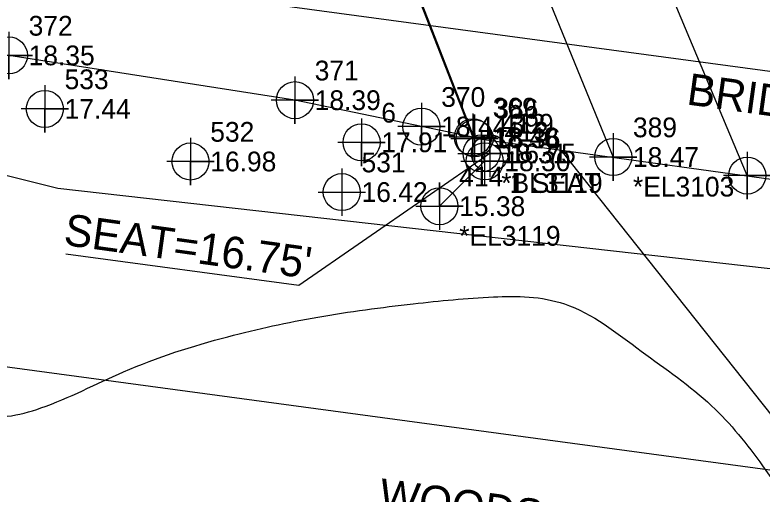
# Model space of a CAD drawing. Extents: x 2627243 to 2636458, y 566398 to 571062.
# Drawn here: x 2634518 to 2634612.5, y 569047.1 to 569107.7 of the extents above; entities that cross this region are included whole.
import ezdxf

# ---------------------------------------------------------------- set-up
doc = ezdxf.new("R2010")
doc.units = 0
for name, color, linetype in [('COGO Default Chain', 7, 'Continuous'), ('Cogo Default Point CELL', 7, 'Continuous'), ('COGO Default Point Elevation', 7, 'Continuous'), ('COGO Default Point Number', 7, 'Continuous'), ('Exist Horizontal Alignment', 7, 'Continuous'), ('Exist Horizontal T-Line Point CELL', 7, 'Continuous'), ('Exist Horizontal T-Line Point Cogo Elevation', 7, 'Continuous'), ('Exist Horizontal T-Line Point Cogo Number', 7, 'Continuous'), ('Exist Hydro Jurisdictional Stream or Body of Water', 7, 'Continuous'), ('Exist Right of Way Line', 7, 'Continuous'), ('Exist Roads EOP', 7, 'Continuous'), ('Exist Roads EOP Cogo Elevation', 7, 'Continuous'), ('Exist Roads EOP Cogo Number', 7, 'Continuous'), ('Exist Roads EOP Cogo Point CELL', 7, 'Continuous'), ('Exist Structure Major Bridge Seam', 7, 'Continuous'), ('Exist Structure Major Bridge Seam Cogo Comment', 7, 'Continuous'), ('Exist Structure Major Bridge Seam Cogo Elevation', 7, 'Continuous'), ('Exist Structure Major Bridge Seam Cogo Number', 7, 'Continuous'), ('Exist Structure Major Bridge Seam Cogo Point CELL', 7, 'Continuous'), ('Exist Structure Major Bridge Seat Cogo Comment', 7, 'Continuous'), ('Exist Structure Major Bridge Seat Cogo Elevation', 7, 'Continuous'), ('Exist Structure Major Bridge Seat Cogo Number', 7, 'Continuous'), ('Exist Structure Major Bridge Seat Cogo Point CELL', 7, 'Continuous'), ('Exist Structure Major Bridge Seat Top Elevation', 7, 'Continuous'), ('Exist Structure Major Bridge WW', 7, 'Continuous'), ('Exist Structure Major Bridge WW Cogo Comment', 7, 'Continuous'), ('Exist Structure Major Bridge WW Cogo Elevation', 7, 'Continuous'), ('Exist Structure Major Bridge WW Cogo Number', 7, 'Continuous'), ('Exist Structure Major Bridge WW Cogo Point CELL', 7, 'Continuous'), ('Exist Structure Major Deck Tunnel Box Culvert', 7, 'Continuous'), ('Exist Structure Major Deck Tunnel Box Culvert Cogo Elevation', 7, 'Continuous'), ('Exist Structure Major Deck Tunnel Box Culvert Cogo Number', 7, 'Continuous'), ('Exist Structure Major Deck Tunnel Box Culvert Cogo Point CELL', 7, 'Continuous'), ('Exist Structure Major Deck Tunnel Box Culvert Text', 7, 'Continuous'), ('Exist Utilities Water UG Line', 7, 'Continuous'), ('Exist Utilities Water UG Line Cogo Elevation', 7, 'Continuous'), ('Exist Utilities Water UG Line Cogo Number', 7, 'Continuous'), ('Exist Utilities Water UG Line Cogo Point CELL', 7, 'Continuous'), ('Exist Vegetation Woods Line', 7, 'Continuous'), ('Exist Vegetation Woods Line Text', 7, 'Continuous')]:
    doc.layers.add(name, color=color, linetype=linetype)

# ---------------------------------------------------------------- blocks, each defined once
blk = doc.blocks.new('EXIST HORIZONTAL T-LINE POINT')
at = {"layer": 'Exist Horizontal T-Line Point CELL'}
blk.add_lwpolyline([(0, 0.06), (0, -0.06), (0, 0), (0.06, 0), (-0.06, 0)], dxfattribs=at)
blk.add_circle((0, 0), 0.0469, dxfattribs=at)
blk = doc.blocks.new('EXIST ROADS EOP COGO POINT')
at = {"layer": 'Exist Roads EOP Cogo Point CELL'}
blk.add_lwpolyline([(0, 0.06), (0, -0.06), (0, 0), (0.06, 0), (-0.06, 0)], dxfattribs=at)
blk.add_circle((0, 0), 0.0469, dxfattribs=at)
blk = doc.blocks.new('EXIST STRUCTURE MAJOR DECK TUNNEL BOX CULVERT COGO POINT')
at = {"layer": 'Exist Structure Major Deck Tunnel Box Culvert Cogo Point CELL'}
blk.add_lwpolyline([(-0.06, 0), (0.06, 0), (0, 0), (0, 0.06), (0, -0.06)], dxfattribs=at)
blk.add_circle((0, 0), 0.0469, dxfattribs=at)
blk = doc.blocks.new('EXIST BRIDGE SEAM COGO POINT')
at = {"layer": 'Exist Structure Major Bridge Seam Cogo Point CELL'}
blk.add_lwpolyline([(0, 0.06), (0, -0.06), (0, 0), (0.06, 0), (-0.06, 0)], dxfattribs=at)
blk.add_circle((0, 0), 0.0469, dxfattribs=at)
blk = doc.blocks.new('EXIST STRUCTURE MAJOR BRIDGE SEAT COGO POINT')
at = {"layer": 'Exist Structure Major Bridge Seat Cogo Point CELL'}
blk.add_lwpolyline([(-0.06, 0), (0.06, 0), (0, 0), (0, 0.06), (0, -0.06)], dxfattribs=at)
blk.add_circle((0, 0), 0.0469, dxfattribs=at)
blk = doc.blocks.new('EXIST STRUCTURE MAJOR BRIDGE WW COGO POINT')
at = {"layer": 'Exist Structure Major Bridge WW Cogo Point CELL'}
blk.add_lwpolyline([(-0.06, 0), (0.06, 0), (0, 0), (0, 0.06), (0, -0.06)], dxfattribs=at)
blk.add_circle((0, 0), 0.0469, dxfattribs=at)
blk = doc.blocks.new('COGO DEFAULT POINT')
at = {"layer": 'Cogo Default Point CELL'}
for points in [[(0, 0.06), (0, 0)], [(-0.06, 0), (0, 0)], [(0, 0), (0.06, 0)], [(0, 0), (0, -0.06)]]:
    blk.add_lwpolyline(points, dxfattribs=at)
blk.add_circle((0, 0), 0.0469, dxfattribs=at)
blk = doc.blocks.new('EXIST UTILITIES WATER UG LINE COGO POINT')
at = {"layer": 'Exist Utilities Water UG Line Cogo Point CELL'}
blk.add_lwpolyline([(0, 0.06), (0, -0.06), (0, 0), (0.06, 0), (-0.06, 0)], dxfattribs=at)
blk.add_circle((0, 0), 0.0469, dxfattribs=at)

msp = doc.modelspace()

# ---------------------------------------------------------------- linework, layer by layer
at = {"layer": 'COGO Default Chain'}
msp.add_line((2634072.78, 569173.542), (2634872.745, 569065.698), dxfattribs=at)
msp.add_line((2634072.78, 569173.542), (2634872.745, 569065.698), dxfattribs=at)
at = {"layer": 'Exist Horizontal Alignment'}
msp.add_line((2634072.78, 569173.542), (2634872.745, 569065.698), dxfattribs=at)
at = {"layer": 'Exist Hydro Jurisdictional Stream or Body of Water'}
msp.add_lwpolyline([(2634587.079, 569090.617), (2634626.068, 569041.558), (2634647.851, 569025.851)], dxfattribs=at)
at = {"layer": 'Exist Right of Way Line'}
msp.add_line((2632403.135, 569348.176), (2634866.065, 569016.146), dxfattribs=at)
at = {"layer": 'Exist Roads EOP'}
msp.add_lwpolyline([(2634467.061, 569130.692), (2634503.954, 569125.774), (2634530.576, 569122.144), (2634545.134, 569120.932), (2634557.62, 569120.167), (2634563.301, 569120.217), (2634565.155, 569119.865), (2634575.95, 569092.263), (2634569.43, 569093.614), (2634553.414, 569096.958), (2634517.197, 569102.627), (2634476.746, 569107.617), (2634427.927, 569114.34)], dxfattribs=at)
at = {"layer": 'Exist Structure Major Bridge Seam'}
for p, q in [((2634582.37, 569117.451), (2634593.704, 569089.767)), ((2634610.676, 569087.421), (2634599.129, 569114.954))]:
    msp.add_line(p, q, dxfattribs=at)
at = {"layer": 'Exist Structure Major Bridge Seat Top Elevation'}
msp.add_lwpolyline([(2634578.097, 569090.224), (2634553.885, 569073.516), (2634524.396, 569077.481)], dxfattribs=at)
at = {"layer": 'Exist Structure Major Bridge WW'}
msp.add_lwpolyline([(2634577.035, 569090.226), (2634577.43, 569089.221), (2634571.708, 569083.54)], dxfattribs=at)
at = {"layer": 'Exist Structure Major Deck Tunnel Box Culvert'}
msp.add_lwpolyline([(2634565.456, 569119.889), (2634666.463, 569105.901), (2634677.512, 569078.102), (2634576.153, 569092.129), (2634565.524, 569119.463)], dxfattribs=at)
at = {"layer": 'Exist Utilities Water UG Line'}
msp.add_lwpolyline([(2634491.938, 569094.669), (2634504.797, 569090.483), (2634523.376, 569085.838), (2634745.287, 569060.808)], dxfattribs=at)
at = {"layer": 'Exist Vegetation Woods Line'}
msp.add_spline([(2634038.3, 568858.082), (2634049.512, 568861.477), (2634056.444, 568863.191), (2634065.7, 568867.403), (2634077.104, 568872.769), (2634086.228, 568877.514), (2634096.458, 568882.137), (2634106.928, 568886.706), (2634118.17, 568891.353), (2634129.289, 568894.894), (2634140.879, 568899.966), (2634152.43, 568905.425), (2634162.621, 568910.434), (2634173.6, 568916.147), (2634183.272, 568921.651), (2634193.292, 568927.58), (2634201.991, 568932.673), (2634213.371, 568939.051), (2634224.536, 568944.471), (2634234.379, 568949.054), (2634246.472, 568953.006), (2634257.777, 568956.254), (2634259.949, 568956.395), (2634271.269, 568960.269), (2634281.46, 568965.278), (2634292.253, 568971.285), (2634302.019, 568976.642), (2634311.637, 568981.905), (2634323.604, 568988.655), (2634333.532, 568994.731), (2634343.884, 569000.459), (2634352.97, 569005.591), (2634362.427, 569010.136), (2634372.974, 569013.932), (2634384.905, 569017.165), (2634395.399, 569020.721), (2634404.601, 569024.694), (2634414.097, 569028.852), (2634426.66, 569034.335), (2634435.955, 569038.161), (2634445.436, 569041.693), (2634456.981, 569044.887), (2634470.18, 569048.716), (2634483.1, 569052.986), (2634494.923, 569055.74), (2634502.436, 569055.56), (2634512.777, 569056.759), (2634516.973, 569056.948), (2634521.239, 569058.003), (2634531.709, 569062.572), (2634544.922, 569067.027), (2634556.305, 569069.502), (2634568.392, 569071.189), (2634578.532, 569072.056), (2634583.061, 569072.044), (2634587.522, 569071.166), (2634597.258, 569065.2), (2634606.152, 569058.289), (2634612.62, 569050.666), (2634619.042, 569041.165), (2634625.851, 569031.702), (2634631.942, 569022.401), (2634637.151, 569012.543), (2634643.544, 569001.789), (2634649.296, 568990.425), (2634651.917, 568979.135), (2634651.819, 568977.017), (2634654.491, 568969.87), (2634659.587, 568947.196), (2634659.868, 568942.853), (2634658.377, 568932.865), (2634654.645, 568921.872), (2634652.096, 568909.982), (2634650.451, 568897.637), (2634648.142, 568885.694), (2634646.087, 568874.323), (2634643.128, 568863.407), (2634638.306, 568853.162), (2634632.201, 568841.694), (2634627.28, 568829.331), (2634625.24, 568818.586), (2634622.799, 568807.176), (2634618.665, 568795.517), (2634614.864, 568783.657), (2634610.422, 568771.186), (2634606.528, 568759.473), (2634602.913, 568747.32), (2634599.806, 568736.311), (2634595.85, 568725.997), (2634595.78, 568725.132)], degree=3, dxfattribs=at)

# ---------------------------------------------------------------- block references
at = {"layer": 'Cogo Default Point CELL', "xscale": 50, "yscale": 50}
msp.add_blockref('COGO DEFAULT POINT', (2634559.345, 569085.327), dxfattribs=at)
at = {"layer": 'Exist Horizontal T-Line Point CELL', "xscale": 50, "yscale": 50}
msp.add_blockref('EXIST HORIZONTAL T-LINE POINT', (2634561.846, 569091.624), dxfattribs=at)
at = {"layer": 'Exist Roads EOP Cogo Point CELL', "xscale": 50, "yscale": 50}
for p in [(2634517.197, 569102.627), (2634553.414, 569096.958), (2634569.43, 569093.614), (2634575.95, 569092.263)]:
    msp.add_blockref('EXIST ROADS EOP COGO POINT', p, dxfattribs=at)
at = {"layer": 'Exist Structure Major Bridge Seam Cogo Point CELL', "xscale": 50, "yscale": 50}
for p in [(2634593.704, 569089.767), (2634610.676, 569087.421)]:
    msp.add_blockref('EXIST BRIDGE SEAM COGO POINT', p, dxfattribs=at)
at = {"layer": 'Exist Structure Major Bridge Seat Cogo Point CELL', "xscale": 50, "yscale": 50}
msp.add_blockref('EXIST STRUCTURE MAJOR BRIDGE SEAT COGO POINT', (2634578.097, 569090.224), dxfattribs=at)
at = {"layer": 'Exist Structure Major Bridge WW Cogo Point CELL', "xscale": 50, "yscale": 50}
for p in [(2634577.035, 569090.226), (2634577.43, 569089.221), (2634571.708, 569083.54)]:
    msp.add_blockref('EXIST STRUCTURE MAJOR BRIDGE WW COGO POINT', p, dxfattribs=at)
at = {"layer": 'Exist Structure Major Deck Tunnel Box Culvert Cogo Point CELL', "xscale": 50, "yscale": 50}
msp.add_blockref('EXIST STRUCTURE MAJOR DECK TUNNEL BOX CULVERT COGO POINT', (2634576.153, 569092.129), dxfattribs=at)
at = {"layer": 'Exist Utilities Water UG Line Cogo Point CELL', "xscale": 50, "yscale": 50}
for p in [(2634521.75, 569095.852), (2634540.191, 569089.202)]:
    msp.add_blockref('EXIST UTILITIES WATER UG LINE COGO POINT', p, dxfattribs=at)

# ---------------------------------------------------------------- texts
at = {"layer": 'COGO Default Point Elevation'}
msp.add_text('16.42', height=2.5, dxfattribs=at).set_placement((2634561.845, 569084.077))
at = {"layer": 'COGO Default Point Number'}
msp.add_text('531', height=2.5, dxfattribs=at).set_placement((2634561.845, 569087.827))
at = {"layer": 'Exist Horizontal T-Line Point Cogo Elevation'}
msp.add_text('17.91', height=2.5, dxfattribs=at).set_placement((2634564.346, 569090.374))
at = {"layer": 'Exist Horizontal T-Line Point Cogo Number'}
msp.add_text('6', height=2.5, dxfattribs=at).set_placement((2634564.346, 569094.124))
at = {"layer": 'Exist Roads EOP Cogo Elevation'}
for s, p in [('18.35', (2634519.697, 569101.377)), ('18.39', (2634555.914, 569095.708)), ('18.44', (2634571.93, 569092.364)), ('18.48', (2634578.45, 569091.013))]:
    msp.add_text(s, height=2.5, dxfattribs=at).set_placement(p)
at = {"layer": 'Exist Roads EOP Cogo Number'}
for s, p in [('372', (2634519.697, 569105.127)), ('371', (2634555.914, 569099.458)), ('370', (2634571.93, 569096.114)), ('369', (2634578.45, 569094.763))]:
    msp.add_text(s, height=2.5, dxfattribs=at).set_placement(p)
at = {"layer": 'Exist Structure Major Bridge Seam Cogo Comment'}
msp.add_text('*EL3103', height=2.5, dxfattribs=at).set_placement((2634596.204, 569084.767))
at = {"layer": 'Exist Structure Major Bridge Seam Cogo Elevation'}
msp.add_text('18.47', height=2.5, dxfattribs=at).set_placement((2634596.204, 569088.517))
at = {"layer": 'Exist Structure Major Bridge Seam Cogo Number'}
msp.add_text('389', height=2.5, dxfattribs=at).set_placement((2634596.204, 569092.267))
at = {"layer": 'Exist Structure Major Bridge Seat Cogo Comment'}
msp.add_text('1 SEAT', height=2.5, dxfattribs=at).set_placement((2634580.597, 569085.224))
at = {"layer": 'Exist Structure Major Bridge Seat Cogo Elevation'}
msp.add_text('16.75', height=2.5, dxfattribs=at).set_placement((2634580.597, 569088.974))
at = {"layer": 'Exist Structure Major Bridge Seat Cogo Number'}
msp.add_text('399', height=2.5, dxfattribs=at).set_placement((2634580.597, 569092.724))
at = {"layer": 'Exist Structure Major Bridge Seat Top Elevation'}
msp.add_text("SEAT=16.75'", height=4, rotation=352.12094, dxfattribs=at).set_placement((2634524.019, 569078.662))
at = {"layer": 'Exist Structure Major Bridge WW Cogo Comment'}
for s, p in [('*BL3119', (2634579.535, 569085.226)), ('*EL3119', (2634574.208, 569078.54))]:
    msp.add_text(s, height=2.5, dxfattribs=at).set_placement(p)
at = {"layer": 'Exist Structure Major Bridge WW Cogo Elevation'}
for s, p in [('18.31', (2634579.535, 569088.976)), ('18.30', (2634579.93, 569087.971)), ('15.38', (2634574.208, 569082.29))]:
    msp.add_text(s, height=2.5, dxfattribs=at).set_placement(p)
at = {"layer": 'Exist Structure Major Bridge WW Cogo Number'}
for s, p in [('412', (2634579.535, 569092.726)), ('413', (2634579.93, 569091.721)), ('414', (2634574.208, 569086.04))]:
    msp.add_text(s, height=2.5, dxfattribs=at).set_placement(p)
at = {"layer": 'Exist Structure Major Deck Tunnel Box Culvert Cogo Elevation'}
msp.add_text('18.36', height=2.5, dxfattribs=at).set_placement((2634578.653, 569090.879))
at = {"layer": 'Exist Structure Major Deck Tunnel Box Culvert Cogo Number'}
msp.add_text('386', height=2.5, dxfattribs=at).set_placement((2634578.653, 569094.629))
at = {"layer": 'Exist Structure Major Deck Tunnel Box Culvert Text'}
msp.add_text('BRIDGE #42 ', height=4, rotation=352.11554, dxfattribs=at).set_placement((2634602.886, 569096.433))
at = {"layer": 'Exist Utilities Water UG Line Cogo Elevation'}
for s, p in [('17.44', (2634524.25, 569094.602)), ('16.98', (2634542.691, 569087.952))]:
    msp.add_text(s, height=2.5, dxfattribs=at).set_placement(p)
at = {"layer": 'Exist Utilities Water UG Line Cogo Number'}
for s, p in [('533', (2634524.25, 569098.352)), ('532', (2634542.691, 569091.702))]:
    msp.add_text(s, height=2.5, dxfattribs=at).set_placement(p)
at = {"layer": 'Exist Vegetation Woods Line Text'}
msp.add_text('WOODS', height=4, rotation=352.32218, dxfattribs=at).set_placement((2634563.89, 569045.133))

doc.saveas('drawing.dxf')
